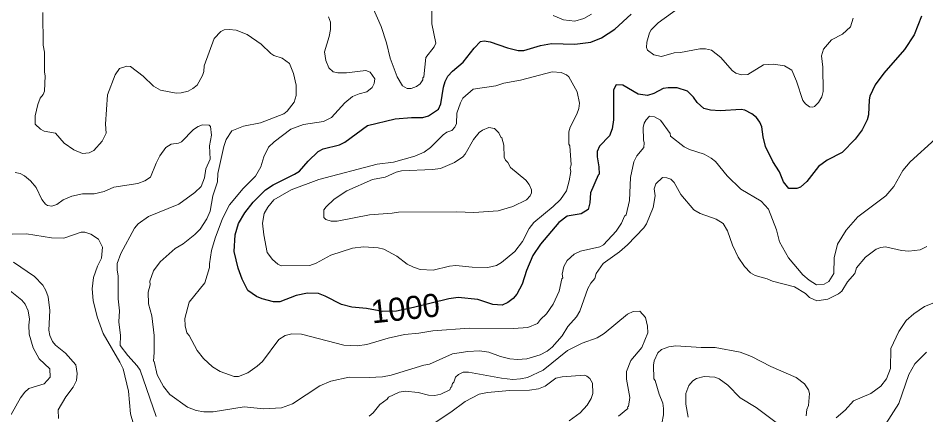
# Model space of a CAD drawing. Extents: x 447.8 to 473.9, y 7733.1 to 7760.8.
# Drawn here: x 459.898 to 463.029, y 7744.218 to 7745.588 of the extents above; entities that cross this region are included whole.
import ezdxf
from ezdxf.enums import TextEntityAlignment as Align

# ---------------------------------------------------------------- set-up
doc = ezdxf.new("R2010")
doc.units = 0
doc.header["$LTSCALE"] = 0.032
doc.layers.add('1', color=7, linetype='Continuous', lineweight=25)
doc.layers.add('2', color=7, linetype='Continuous', lineweight=13)
doc.layers.add('61', color=7, linetype='Continuous')

msp = doc.modelspace()

# ---------------------------------------------------------------- linework, layer by layer
at = {"layer": '1'}
for points in [[(460.6567, 7744.7247), (460.6432, 7744.7817), (460.6463, 7744.8394), (460.658, 7744.879), (460.6803, 7744.9159), (460.7087, 7744.9525), (460.7508, 7744.9948), (460.7781, 7745.013), (460.8513, 7745.0488), (460.8681, 7745.0599), (460.8986, 7745.0944), (460.9334, 7745.1274), (460.9503, 7745.1364), (461.0059, 7745.1509), (461.025, 7745.1597), (461.1026, 7745.2172), (461.1982, 7745.2406), (461.2548, 7745.2453), (461.294, 7745.2454), (461.3136, 7745.2511), (461.3476, 7745.2734), (461.3565, 7745.292), (461.3647, 7745.3499), (461.3706, 7745.3695), (461.3805, 7745.3877), (461.3957, 7745.4054), (461.4333, 7745.4366), (461.471, 7745.4849), (461.4934, 7745.5072), (461.5054, 7745.5099), (461.5262, 7745.5067), (461.5857, 7745.4861), (461.6224, 7745.477), (461.6428, 7745.4762), (461.7, 7745.4939), (461.7378, 7745.5002), (461.8177, 7745.4979), (461.8732, 7745.5052), (461.9099, 7745.5204), (461.9566, 7745.5505), (462.0123, 7745.602)], [(463.0144, 7745.5956), (462.9894, 7745.5307), (462.9551, 7745.4804), (462.8842, 7745.3981), (462.8548, 7745.3575), (462.8358, 7745.3183), (462.8332, 7745.3066), (462.8315, 7745.2537), (462.8265, 7745.237), (462.8092, 7745.2023), (462.7859, 7745.1698), (462.7407, 7745.1247), (462.6891, 7745.0972), (462.6586, 7745.0763), (462.6184, 7745.0235), (462.5973, 7745.0041), (462.5838, 7745), (462.5569, 7744.9993), (462.5382, 7745.0224), (462.5245, 7745.0577), (462.5014, 7745.0927), (462.4762, 7745.1446), (462.4679, 7745.1788), (462.4637, 7745.2125), (462.4565, 7745.229), (462.4447, 7745.2449), (462.4292, 7745.2578), (462.4053, 7745.2708), (462.3925, 7745.2725), (462.3193, 7745.2686), (462.2868, 7745.2709), (462.2634, 7745.2757), (462.2402, 7745.2963), (462.2277, 7745.3153), (462.2064, 7745.3365), (462.171, 7745.3479), (462.1403, 7745.348), (462.1229, 7745.3447), (462.0908, 7745.3279), (462.0688, 7745.3215), (462.0369, 7745.3257), (461.9844, 7745.3563), (461.9605, 7745.3575), (461.9516, 7745.3406), (461.9513, 7745.2375), (461.9474, 7745.2056), (461.9384, 7745.1813), (461.9029, 7745.1457), (461.8955, 7745.1274), (461.8953, 7745.1087), (461.9016, 7745.0741), (461.9017, 7745.0488), (461.8984, 7745.0462), (461.8719, 7744.9851), (461.8704, 7744.9504), (461.8646, 7744.9272), (461.8401, 7744.9119), (461.7914, 7744.9047), (461.7628, 7744.882), (461.6994, 7744.8073), (461.6739, 7744.7688), (461.651, 7744.7165), (461.6362, 7744.6694), (461.6177, 7744.6343), (461.6052, 7744.6196), (461.5871, 7744.6063), (461.5674, 7744.5965), (461.5358, 7744.5993), (461.4832, 7744.6168), (461.4156, 7744.6232), (461.3835, 7744.6191), (461.2622, 7744.589), (461.2027, 7744.5762), (461.1556, 7744.5752), (461.0993, 7744.5857), (461.0495, 7744.5894), (461.0132, 7744.5994), (460.9569, 7744.628), (460.9337, 7744.6368), (460.8963, 7744.6377), (460.8564, 7744.6297), (460.8002, 7744.6084), (460.7791, 7744.6081)], [(460.7791, 7744.6081), (460.7396, 7744.6182), (460.7206, 7744.6272), (460.6898, 7744.6475), (460.6703, 7744.6862), (460.6567, 7744.7247)]]:
    msp.add_lwpolyline(points, dxfattribs=at)
at = {"layer": '2'}
for points in [[(461.1208, 7745.6271), (461.1505, 7745.5595), (461.1683, 7745.5031), (461.1807, 7745.4505), (461.2057, 7745.3855), (461.2243, 7745.3544), (461.2396, 7745.3448), (461.2541, 7745.3448), (461.2721, 7745.3526), (461.2842, 7745.3615), (461.2939, 7745.3753), (461.2941, 7745.3818), (461.2972, 7745.3852), (461.3037, 7745.4521), (461.3325, 7745.4896), (461.3387, 7745.502), (461.3246, 7745.5685), (461.3247, 7745.6255)], [(462.1839, 7745.6287), (462.1063, 7745.5719), (462.0817, 7745.548), (462.0754, 7745.5373), (462.0666, 7745.5056), (462.0652, 7745.4874), (462.0687, 7745.4776), (462.0913, 7745.4611), (462.1169, 7745.4554), (462.1614, 7745.4681), (462.1827, 7745.4695), (462.2492, 7745.4817), (462.2691, 7745.4817), (462.2893, 7745.4778), (462.3216, 7745.4522), (462.3614, 7745.4072), (462.3733, 7745.398), (462.3931, 7745.3921), (462.4147, 7745.3938), (462.4696, 7745.4264), (462.5035, 7745.4296), (462.5419, 7745.4236), (462.5668, 7745.4088), (462.5828, 7745.371), (462.6052, 7745.3037), (462.6139, 7745.2922), (462.628, 7745.2814), (462.6388, 7745.2806), (462.645, 7745.2833), (462.6583, 7745.2966), (462.6708, 7745.3168), (462.6744, 7745.3352), (462.6735, 7745.4191)], [(459.9827, 7745.6082), (459.9843, 7745.4954), (459.9883, 7745.4704), (459.9883, 7745.4013), (459.9916, 7745.3893), (459.9889, 7745.3361), (459.9842, 7745.3247), (459.974, 7745.3115), (459.9659, 7745.2905), (459.9571, 7745.2507), (459.9571, 7745.2216), (459.9745, 7745.2044), (459.988, 7745.1981), (460.0264, 7745.1908), (460.0562, 7745.1567), (460.0904, 7745.1338), (460.1194, 7745.1211), (460.1424, 7745.1225), (460.1589, 7745.1313), (460.1882, 7745.1633), (460.2017, 7745.1907), (460.1992, 7745.2222), (460.2056, 7745.3233), (460.2323, 7745.3919), (460.2478, 7745.4142), (460.2729, 7745.4224), (460.2854, 7745.4216), (460.3295, 7745.3882), (460.3642, 7745.3528), (460.3885, 7745.3398), (460.4434, 7745.3295), (460.4604, 7745.3302), (460.4838, 7745.3365), (460.5, 7745.3449), (460.5151, 7745.357), (460.5336, 7745.3903), (460.5384, 7745.4044), (460.539, 7745.4232), (460.5744, 7745.5181), (460.5974, 7745.5423), (460.6081, 7745.5475), (460.626, 7745.5492), (460.6495, 7745.5471), (460.6883, 7745.5313), (460.7359, 7745.4988), (460.7697, 7745.4661), (460.7803, 7745.4594), (460.8086, 7745.4504), (460.8339, 7745.4319), (460.848, 7745.3971), (460.8565, 7745.3572), (460.8564, 7745.3206), (460.8499, 7745.2982), (460.8257, 7745.2675), (460.8143, 7745.258), (460.7336, 7745.2262), (460.6755, 7745.2149), (460.635, 7745.1993), (460.616, 7745.1691), (460.6077, 7745.1448), (460.5872, 7745.052), (460.5854, 7745.0224), (460.5696, 7744.975), (460.5599, 7744.9217), (460.5492, 7744.8953), (460.5255, 7744.8597)], [(461.7435, 7745.5972), (461.7795, 7745.582), (461.8186, 7745.578), (461.8497, 7745.5866), (461.8761, 7745.6019)], [(463.226, 7745.5987), (463.2251, 7745.5468), (463.2358, 7745.5119), (463.2428, 7745.4598), (463.2485, 7745.4393), (463.2491, 7745.4025), (463.2436, 7745.3707), (463.2341, 7745.3393), (463.2135, 7745.3036), (463.1761, 7745.267), (463.146, 7745.2511), (463.1109, 7745.2233), (463.0613, 7745.1705), (462.9753, 7745.0914), (462.9502, 7745.0615), (462.9192, 7745.007), (462.8913, 7744.9741)], [(461.1008, 7745.3339), (461.1186, 7745.349), (461.1258, 7745.3629), (461.1288, 7745.3783), (461.1127, 7745.4017), (461.0972, 7745.4071), (461.0302, 7745.3993), (461.0008, 7745.3988), (460.9849, 7745.4031), (460.9695, 7745.417), (460.9591, 7745.4422), (460.9551, 7745.4718), (460.9711, 7745.5246), (460.9752, 7745.5485), (460.975, 7745.5749), (460.9683, 7745.5926)], [(462.6735, 7745.4191), (462.6696, 7745.4585), (462.6761, 7745.4816), (462.7038, 7745.5128), (462.7415, 7745.5334), (462.7687, 7745.5587), (462.7786, 7745.5884)], [(460.9512, 7745.2313), (460.979, 7745.2454), (461.0252, 7745.2955), (461.0518, 7745.3175), (461.0738, 7745.3268), (461.1008, 7745.3339)], [(462.7114, 7744.7058), (462.6949, 7744.6785), (462.6786, 7744.6689), (462.6514, 7744.6672), (462.6271, 7744.6827), (462.6052, 7744.7013), (462.5554, 7744.7601), (462.5244, 7744.8159), (462.5139, 7744.8565), (462.4868, 7744.9279), (462.4611, 7744.9561), (462.3905, 7744.9977), (462.3443, 7745.0439), (462.3034, 7745.0936), (462.2889, 7745.105), (462.2642, 7745.1185), (462.2136, 7745.1342), (462.1953, 7745.1434), (462.1486, 7745.18), (462.1469, 7745.1897), (462.1137, 7745.2353), (462.0927, 7745.2468), (462.076, 7745.2501), (462.0638, 7745.237), (462.0575, 7745.225), (462.054, 7745.21), (462.0548, 7745.1684), (462.0578, 7745.1574), (462.0558, 7745.1419), (462.0319, 7745.1125), (462.0217, 7745.0924), (462.0107, 7745.0373), (462.0074, 7744.9584), (461.9948, 7744.9093), (461.9899, 7744.9038), (461.9796, 7744.8801), (461.9606, 7744.8522), (461.9166, 7744.8048), (461.9045, 7744.7988), (461.8375, 7744.7836), (461.8154, 7744.7725), (461.792, 7744.7507), (461.7798, 7744.7309), (461.7744, 7744.7041), (461.7766, 7744.6917), (461.7735, 7744.6879), (461.7642, 7744.6452), (461.744, 7744.5999), (461.721, 7744.5669), (461.6995, 7744.5477), (461.69, 7744.5329), (461.6566, 7744.5199), (461.6065, 7744.5162), (461.4536, 7744.5174), (461.3281, 7744.5079), (461.2803, 7744.4999), (461.2309, 7744.4957), (461.1741, 7744.4823), (461.1004, 7744.4606), (461.0676, 7744.4566), (461.0212, 7744.4582), (460.8753, 7744.4967), (460.842, 7744.4982), (460.8192, 7744.4917), (460.7977, 7744.478), (460.7406, 7744.4026), (460.7227, 7744.3859), (460.6901, 7744.3634), (460.6576, 7744.3508), (460.6436, 7744.3507), (460.5944, 7744.368), (460.5681, 7744.3841), (460.5375, 7744.4123), (460.5154, 7744.4405), (460.4876, 7744.4918), (460.4799, 7744.5012), (460.4736, 7744.525), (460.4733, 7744.5502), (460.4874, 7744.6066), (460.5421, 7744.6738), (460.5581, 7744.7272), (460.5575, 7744.7391), (460.5651, 7744.7854), (460.5772, 7744.8278), (460.6033, 7744.8961), (460.6274, 7744.9432), (460.6742, 7744.9998), (460.7171, 7745.042), (460.7352, 7745.075), (460.7452, 7745.1097), (460.7617, 7745.1424), (460.7808, 7745.1611), (460.839, 7745.2053), (460.8827, 7745.2214), (460.9512, 7745.2313)], [(460.5618, 7745.2137), (460.5572, 7745.2189), (460.5342, 7745.2196), (460.5184, 7745.2138), (460.5028, 7745.2034), (460.4618, 7745.161), (460.4505, 7745.1566), (460.4253, 7745.1531), (460.4072, 7745.1415), (460.3868, 7745.1124), (460.374, 7745.0877), (460.3545, 7745.0386), (460.335, 7745.0262), (460.3109, 7745.0173), (460.228, 7745.0048), (460.1943, 7744.9897), (460.1606, 7744.9817), (460.1202, 7744.9816), (460.0834, 7744.9729), (460.053, 7744.9606), (460.0315, 7744.944), (460.0135, 7744.9386), (459.9992, 7744.9406), (459.9917, 7744.9456), (459.9791, 7744.9614), (459.9602, 7745.0032), (459.9406, 7745.0261), (459.9196, 7745.044), (459.9049, 7745.0521), (459.8872, 7745.0553)], [(460.5405, 7745.0369), (460.5451, 7745.0683), (460.5607, 7745.1016), (460.5583, 7745.1477), (460.5647, 7745.184), (460.5618, 7745.2137)], [(460.3741, 7744.2123), (460.3182, 7744.3722), (460.3087, 7744.3878), (460.2764, 7744.4224), (460.25, 7744.4572), (460.2504, 7744.4918), (460.2457, 7744.5396), (460.2472, 7744.5771), (460.2424, 7744.6189), (460.2424, 7744.6974), (460.2391, 7744.7183), (460.2393, 7744.7409), (460.2519, 7744.7753), (460.299, 7744.8624), (460.3119, 7744.8772), (460.3475, 7744.9026), (460.4522, 7744.9454), (460.5069, 7744.9864), (460.5292, 7745.0064), (460.5405, 7745.0369)], [(460.3644, 7744.7157), (460.3524, 7744.6799), (460.353, 7744.6676), (460.3467, 7744.6415), (460.347, 7744.6019), (460.3593, 7744.5598), (460.3674, 7744.4921), (460.3675, 7744.433), (460.3643, 7744.4039), (460.3676, 7744.4023), (460.3778, 7744.3559), (460.3991, 7744.316), (460.4215, 7744.2887), (460.4823, 7744.2448), (460.5121, 7744.2329), (460.5379, 7744.2282), (460.571, 7744.2282), (460.6778, 7744.2457), (460.7446, 7744.2385), (460.8064, 7744.2425), (460.844, 7744.256), (460.9382, 7744.3183), (460.9769, 7744.3348), (461.0394, 7744.3484), (461.1088, 7744.3468), (461.1551, 7744.3498), (461.185, 7744.3555), (461.2975, 7744.3893), (461.3165, 7744.3925), (461.3959, 7744.4284), (461.4492, 7744.4373), (461.4899, 7744.4389), (461.5214, 7744.4342), (461.5624, 7744.4195), (461.5935, 7744.4117), (461.62, 7744.4092), (461.6527, 7744.4113), (461.6986, 7744.4256), (461.7223, 7744.4375), (461.7396, 7744.4516), (461.7746, 7744.4905), (461.7941, 7744.5229), (461.8238, 7744.5569), (461.836, 7744.5755), (461.8633, 7744.6541), (461.8735, 7744.6725), (461.8869, 7744.6888), (461.8923, 7744.7058), (461.9162, 7744.7403), (461.9725, 7744.7814), (462.0001, 7744.8051), (462.0559, 7744.8642), (462.0659, 7744.8782), (462.089, 7744.9337), (462.0956, 7744.9743), (462.0917, 7744.9981), (462.0982, 7745.0162), (462.1202, 7745.0377), (462.1357, 7745.0369), (462.1492, 7745.0317), (462.1613, 7745.0207), (462.1843, 7744.9787), (462.2293, 7744.9257), (462.2509, 7744.9136), (462.3059, 7744.8941), (462.3297, 7744.879), (462.345, 7744.8531), (462.3619, 7744.8042), (462.3817, 7744.763), (462.4038, 7744.7302), (462.4238, 7744.7089), (462.4409, 7744.6988), (462.4821, 7744.6879), (462.5002, 7744.6793), (462.5766, 7744.6601), (462.6136, 7744.6375), (462.628, 7744.6236), (462.6535, 7744.6121), (462.6915, 7744.6172), (462.7275, 7744.6358), (462.7397, 7744.6453), (462.7585, 7744.6778), (462.7841, 7744.7058), (462.7902, 7744.7252), (462.8214, 7744.7631), (462.8577, 7744.7903), (462.8734, 7744.7965), (462.8895, 7744.798), (462.9456, 7744.7852), (462.9703, 7744.7837), (463.0097, 7744.7877), (463.0324, 7744.7992)], [(462.8913, 7744.9741), (462.7949, 7744.9024), (462.7542, 7744.8563), (462.7242, 7744.8077), (462.7129, 7744.7602), (462.7114, 7744.7058)], [(459.8777, 7744.842), (459.9271, 7744.8428), (460.0131, 7744.8293), (460.0558, 7744.8281), (460.1149, 7744.8493), (460.1284, 7744.8492), (460.1481, 7744.8426), (460.1756, 7744.8248)], [(460.5255, 7744.8597), (460.5077, 7744.8407), (460.4671, 7744.8086), (460.4392, 7744.7928), (460.3873, 7744.7465), (460.3644, 7744.7157)], [(460.1756, 7744.8248), (460.1883, 7744.7972), (460.1859, 7744.7592), (460.1711, 7744.731), (460.1575, 7744.6924), (460.1527, 7744.6531)], [(460.0371, 7744.2053), (460.0359, 7744.2357), (460.0621, 7744.2801), (460.0882, 7744.314), (460.0991, 7744.3369), (460.102, 7744.3602), (460.0964, 7744.3909), (460.0611, 7744.4309), (460.0272, 7744.4584), (460.0166, 7744.4714), (460.0076, 7744.4918), (460.0036, 7744.5103), (460.0074, 7744.578), (460.0019, 7744.6256), (459.9937, 7744.6475), (459.9828, 7744.6661), (459.9542, 7744.6954), (459.8815, 7744.7458)], [(459.8698, 7744.6461), (459.9105, 7744.6144), (459.9217, 7744.6), (459.9328, 7744.5771), (459.937, 7744.5486), (459.9346, 7744.5278), (459.936, 7744.4961), (459.9491, 7744.4489), (459.9708, 7744.4116), (460.0066, 7744.3763), (460.0084, 7744.3482), (459.9877, 7744.3253), (459.9346, 7744.3089), (459.9205, 7744.2965), (459.9061, 7744.2772), (459.8738, 7744.2194)], [(460.1527, 7744.6531), (460.1565, 7744.6127), (460.1704, 7744.5562), (460.191, 7744.4985), (460.2489, 7744.4002), (460.2599, 7744.3768), (460.279, 7744.3), (460.2856, 7744.221), (460.3089, 7744.1422)], [(463.0915, 7744.6185), (463.0243, 7744.592), (462.9873, 7744.5674), (462.9612, 7744.5438), (462.9364, 7744.5061), (462.9086, 7744.4474), (462.9068, 7744.3775), (462.8931, 7744.3426), (462.8741, 7744.3165), (462.839, 7744.2916), (462.7796, 7744.2664), (462.7513, 7744.2338), (462.7195, 7744.2074)], [(461.9692, 7744.2132), (462.0009, 7744.2403), (462.0003, 7744.2451), (462.0036, 7744.2473), (462.0082, 7744.2774), (461.9963, 7744.3408), (461.9963, 7744.3671), (462.0116, 7744.4055), (462.049, 7744.45), (462.07, 7744.5015), (462.0686, 7744.5243), (462.0619, 7744.5538), (462.042, 7744.5756), (462.019, 7744.5752), (461.9997, 7744.5656), (461.9196, 7744.4984), (461.8949, 7744.4845), (461.8436, 7744.4652), (461.7929, 7744.4399), (461.7085, 7744.3719), (461.6551, 7744.3472), (461.6314, 7744.342), (461.6043, 7744.3404), (461.5654, 7744.3445), (461.4515, 7744.3651), (461.4333, 7744.365), (461.4166, 7744.3574), (461.4064, 7744.3481), (461.4006, 7744.331), (461.3958, 7744.3264), (461.3933, 7744.3141), (461.3901, 7744.3135), (461.3875, 7744.3048), (461.3559, 7744.2888), (461.3348, 7744.2843), (461.3129, 7744.2856), (461.278, 7744.2954), (461.2324, 7744.2994), (461.2118, 7744.2958), (461.1754, 7744.2792), (461.1707, 7744.2717), (461.1457, 7744.2537), (461.1222, 7744.2247), (461.1086, 7744.2128)], [(462.6167, 7744.2143), (462.6181, 7744.236), (462.6247, 7744.2504), (462.6279, 7744.2922), (462.6244, 7744.3042), (462.6104, 7744.3248), (462.5814, 7744.3468), (462.4943, 7744.3855), (462.4278, 7744.4195), (462.3887, 7744.4342), (462.3027, 7744.4501), (462.2537, 7744.4502), (462.1668, 7744.4565), (462.1424, 7744.4534), (462.1176, 7744.4441), (462.1051, 7744.4322), (462.0919, 7744.4042), (462.0896, 7744.3897), (462.0909, 7744.3422), (462.0956, 7744.337), (462.1089, 7744.2898), (462.1218, 7744.2588), (462.1246, 7744.2397), (462.1238, 7744.2183), (462.118, 7744.1885)], [(462.6171, 7744.0741), (462.6872, 7744.0918), (462.7454, 7744.0972), (462.8145, 7744.1227), (462.8465, 7744.1422), (462.8906, 7744.187), (462.9358, 7744.2572), (462.971, 7744.3578), (462.9914, 7744.3945), (463.0309, 7744.4347)], [(461.3365, 7744.1915), (461.3909, 7744.2272), (461.4396, 7744.2638), (461.4883, 7744.289), (461.5174, 7744.2954), (461.5927, 7744.3017), (461.6614, 7744.3034), (461.6933, 7744.3079), (461.7155, 7744.3165), (461.7526, 7744.3442), (461.7747, 7744.3498), (461.8511, 7744.3546), (461.8593, 7744.3521), (461.8696, 7744.344), (461.8791, 7744.3278), (461.8807, 7744.2913), (461.8745, 7744.2742), (461.8611, 7744.2519), (461.8367, 7744.2249), (461.7992, 7744.1971)], [(462.2095, 7744.21), (462.2017, 7744.2543), (462.2015, 7744.2913), (462.2112, 7744.319), (462.225, 7744.3358), (462.2382, 7744.343), (462.265, 7744.3506), (462.3018, 7744.3484), (462.316, 7744.3427), (462.3463, 7744.3205), (462.3891, 7744.2772), (462.4441, 7744.2429), (462.5223, 7744.1849)]]:
    msp.add_lwpolyline(points, dxfattribs=at)
for points in [[(461.8255, 7745.2567), (461.832, 7745.2764), (461.8343, 7745.295), (461.8261, 7745.3342), (461.7974, 7745.3855), (461.79, 7745.3926), (461.7715, 7745.4001), (461.7397, 7745.4024), (461.6307, 7745.3743), (461.5733, 7745.364), (461.5462, 7745.3543), (461.468, 7745.3425), (461.4324, 7745.3115), (461.4235, 7745.2957), (461.4112, 7745.26), (461.4095, 7745.2248), (461.4044, 7745.2115), (461.3934, 7745.1998), (461.3764, 7745.1943), (461.3643, 7745.1856), (461.3203, 7745.1409), (461.2986, 7745.1258), (461.2662, 7745.111), (461.1927, 7745.0906), (461.1369, 7745.0842), (460.935, 7745.0309), (460.8398, 7744.9948), (460.7797, 7744.9609), (460.7588, 7744.935), (460.7461, 7744.9131), (460.741, 7744.8802), (460.7454, 7744.8399), (460.7567, 7744.7787), (460.7757, 7744.7548), (460.7941, 7744.7386), (460.8056, 7744.7332), (460.9042, 7744.7339), (460.9263, 7744.7424), (460.9763, 7744.769), (461.0517, 7744.794), (461.0893, 7744.7981), (461.1398, 7744.7949), (461.1597, 7744.7899), (461.2037, 7744.7663), (461.2398, 7744.7386), (461.262, 7744.7275), (461.2845, 7744.7203), (461.3293, 7744.7178), (461.3858, 7744.7316), (461.4072, 7744.7339), (461.4637, 7744.7284), (461.5176, 7744.7268), (461.5479, 7744.7342), (461.5653, 7744.7437), (461.6113, 7744.7826), (461.6379, 7744.8172), (461.6605, 7744.8611), (461.6764, 7744.8828), (461.7432, 7744.9371), (461.7694, 7744.9623), (461.7891, 7744.9914), (461.7991, 7745.026), (461.8045, 7745.0586), (461.8024, 7745.0705), (461.8054, 7745.0812), (461.8009, 7745.1473), (461.7975, 7745.1535), (461.7975, 7745.1961), (461.8025, 7745.2122)], [(461.604, 7744.9378), (461.6515, 7744.9608), (461.6646, 7744.9746), (461.6692, 7744.9844), (461.6692, 7744.9949), (461.661, 7745.0132), (461.6491, 7745.0289), (461.5961, 7745.0726), (461.5873, 7745.0898), (461.579, 7745.0972), (461.5746, 7745.1084), (461.5729, 7745.1493), (461.5668, 7745.1748), (461.5634, 7745.1767), (461.5561, 7745.1924), (461.5408, 7745.2076), (461.5218, 7745.21), (461.5003, 7745.2017), (461.4886, 7745.1938), (461.4687, 7745.1688), (461.4403, 7745.1187), (461.4319, 7745.1093), (461.4033, 7745.0892), (461.355, 7745.0689), (461.3272, 7745.065), (461.22, 7745.0609), (461.2014, 7745.0562), (461.1637, 7745.0389), (461.1206, 7745.0304), (461.0312, 7744.9912), (460.9879, 7744.9628), (460.9609, 7744.937), (460.9529, 7744.9258), (460.9528, 7744.9), (460.9597, 7744.8931), (460.9776, 7744.8872), (460.9986, 7744.8871), (461.1097, 7744.9094), (461.1886, 7744.9143), (461.2104, 7744.9182), (461.4101, 7744.9191), (461.4695, 7744.9167), (461.5542, 7744.9221)]]:
    msp.add_lwpolyline(points, close=True, dxfattribs=at)

# ---------------------------------------------------------------- texts
at = {"layer": '61'}
msp.add_text('1000', height=0.08, rotation=6.153, dxfattribs=at).set_placement((461.2378, 7744.5462), align=Align.CENTER)

doc.saveas('drawing.dxf')
